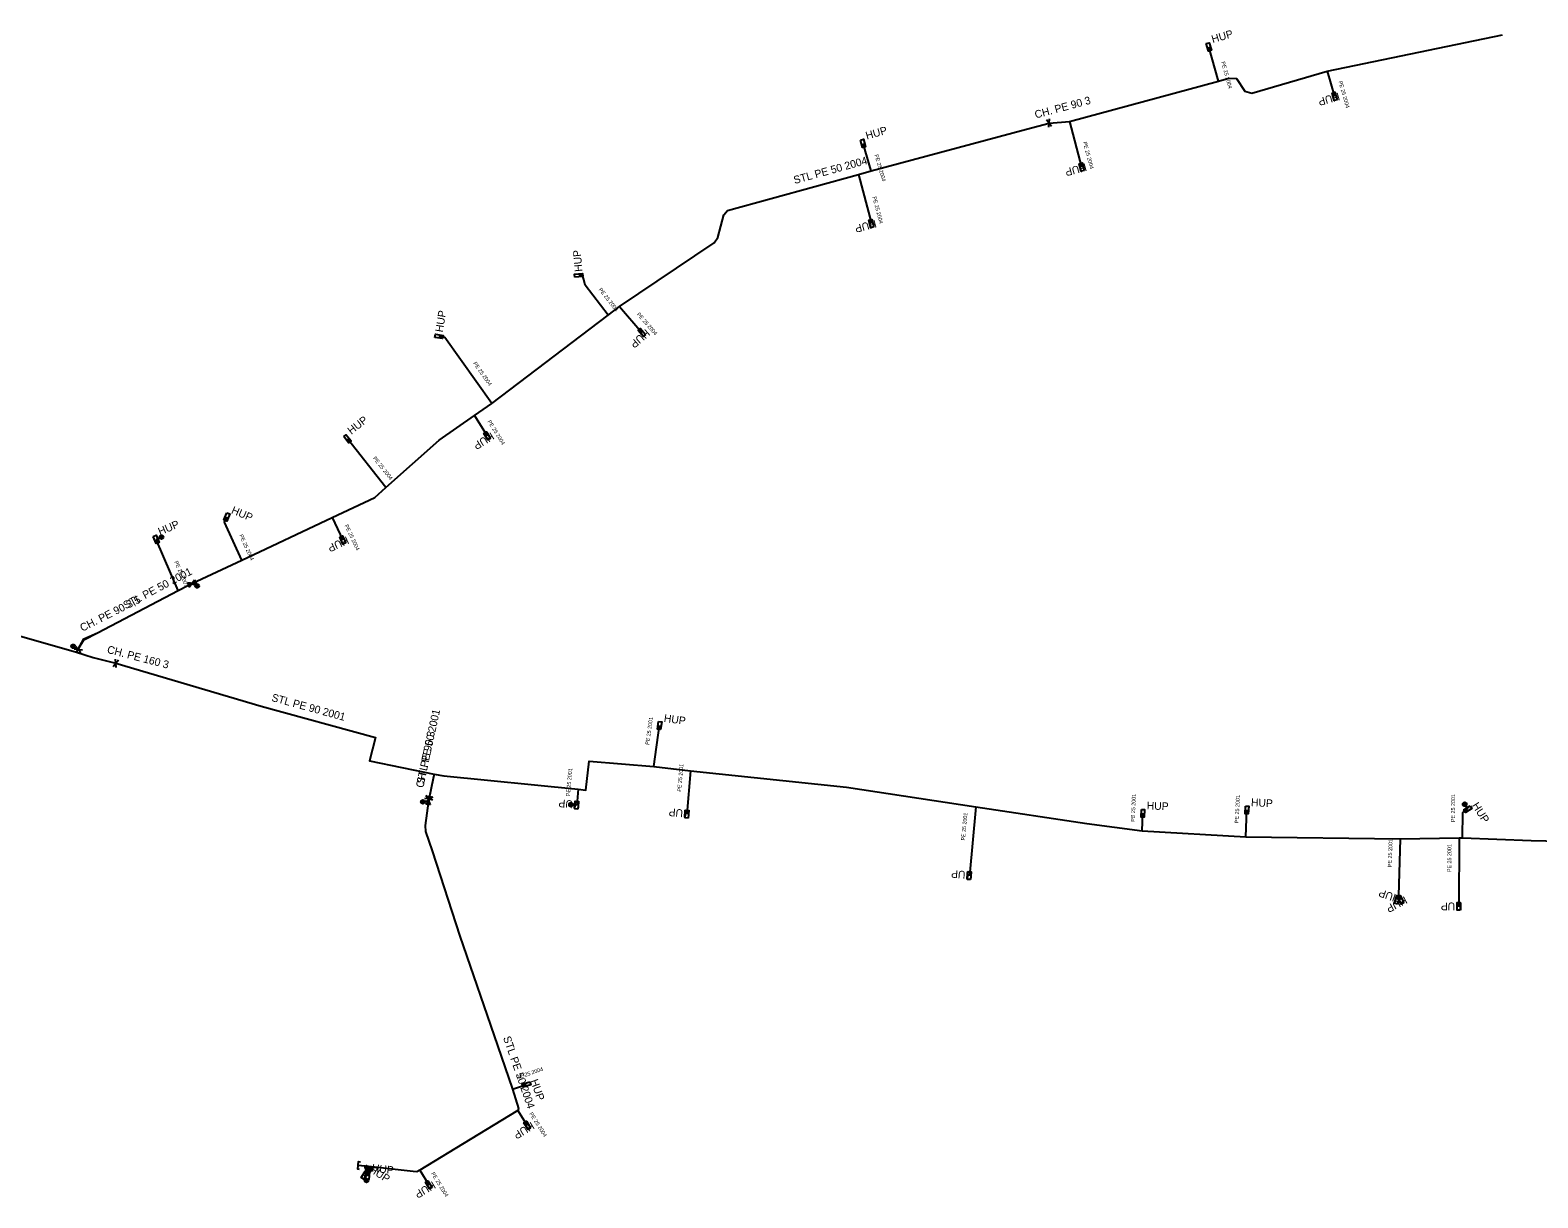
# Model space of a CAD drawing. Extents: x -724831 to -724223, y -1048957 to -1048806.
# Drawn here: x -724613.1 to -724418.3, y -1048956.6 to -1048805.7 of the extents above; entities that cross this region are included whole.
import ezdxf

# ---------------------------------------------------------------- set-up
doc = ezdxf.new("R2010")
doc.units = 0
for name, color, linetype in [('ST OP Chráni_ka - provoz', 7, 'Continuous'), ('ST Úsek p_ípojky - provoz', 7, 'Continuous'), ('ST Úsek plynovodu - provoz', 7, 'Continuous'), ('ST_HUP_22_23_popis', 7, 'Continuous'), ('Vrstva 1', 7, 'Continuous')]:
    doc.layers.add(name, color=color, linetype=linetype)

msp = doc.modelspace()

# ---------------------------------------------------------------- linework, layer by layer
at = {"layer": 'ST OP Chráni_ka - provoz'}
for points in [[(-724484.31, -1048818.51), (-724481.41, -1048817.73)], [(-724606.84, -1048885.7), (-724606.12, -1048884.49)], [(-724606.12, -1048884.49), (-724604.36, -1048883.6)], [(-724604.91, -1048886.77), (-724601.99, -1048887.53)], [(-724560.98, -1048902.42), (-724561.59, -1048905.36)]]:
    msp.add_lwpolyline(points, dxfattribs=at)
at = {"layer": 'ST Úsek p_ípojky - provoz'}
for points in [[(-724459.52, -1048812.33), (-724460.76, -1048807.9)], [(-724445.46, -1048811.01), (-724444.52, -1048814.28)], [(-724478.78, -1048817.53), (-724477.21, -1048823.42)], [(-724504.41, -1048823.92), (-724505.45, -1048820.37)], [(-724506.05, -1048824.38), (-724504.37, -1048830.72)], [(-724538.36, -1048842.55), (-724541.37, -1048838.66), (-724541.53, -1048837.96), (-724541.72, -1048837.36), (-724542.19, -1048837.4)], [(-724536.91, -1048841.45), (-724534.02, -1048844.79)], [(-724553.42, -1048853.95), (-724559.47, -1048845.43), (-724560.24, -1048845.31)], [(-724555.66, -1048855.51), (-724554.02, -1048858.15)], [(-724567.1, -1048864.83), (-724572.07, -1048858.52)], [(-724585.7, -1048874.22), (-724587.94, -1048869.29), (-724587.66, -1048868.62)], [(-724574.04, -1048868.71), (-724572.68, -1048871.61)], [(-724593.95, -1048878.12), (-724596.78, -1048871.53)], [(-724532.47, -1048900.89), (-724531.73, -1048895.59)], [(-724527.72, -1048901.44), (-724528.2, -1048907.02)], [(-724542.25, -1048903.78), (-724542.44, -1048905.86)], [(-724490.88, -1048906.1), (-724491.71, -1048914.98)], [(-724456, -1048909.98), (-724455.84, -1048906.49)], [(-724427.98, -1048910.08), (-724427.96, -1048906.8), (-724427.3, -1048906.39)], [(-724469.39, -1048909.2), (-724469.3, -1048906.92)], [(-724436.03, -1048910.2), (-724436.25, -1048917.59)], [(-724428.43, -1048910.09), (-724428.47, -1048918.95)], [(-724436.25, -1048917.59), (-724436.43, -1048918.1)], [(-724436.25, -1048917.59), (-724435.98, -1048918.1)], [(-724550.73, -1048942.58), (-724548.93, -1048941.97)], [(-724550.05, -1048945.3), (-724548.83, -1048947.24)], [(-724569.49, -1048953.1), (-724569.85, -1048953.65)], [(-724569.39, -1048953.11), (-724569.49, -1048953.1)], [(-724569.4, -1048953.21), (-724569.46, -1048953.71)], [(-724569.33, -1048952.57), (-724569.39, -1048953.11), (-724569.4, -1048953.21)], [(-724562.71, -1048953.04), (-724561.57, -1048954.92)]]:
    msp.add_lwpolyline(points, dxfattribs=at)
at = {"layer": 'ST Úsek plynovodu - provoz'}
for points in [[(-724592.17, -1048877.22), (-724585.7, -1048874.22), (-724574.04, -1048868.71), (-724568.53, -1048866.11), (-724567.1, -1048864.83), (-724560.21, -1048858.69), (-724555.66, -1048855.51), (-724553.42, -1048853.95), (-724538.36, -1048842.55), (-724536.91, -1048841.45), (-724524.69, -1048833.2), (-724524.22, -1048832.5), (-724523.43, -1048829.58), (-724522.95, -1048829.04), (-724506.05, -1048824.38), (-724504.41, -1048823.92), (-724484.31, -1048818.51), (-724481.41, -1048817.73), (-724478.78, -1048817.53), (-724459.52, -1048812.33), (-724458.17, -1048811.95), (-724457.19, -1048811.98), (-724456.11, -1048813.59), (-724455.2, -1048813.85), (-724445.46, -1048811.01), (-724422.83, -1048806.33)], [(-724755.26, -1048907.64), (-724751.23, -1048905.91), (-724751.02, -1048905.85), (-724751.07, -1048905.68), (-724752.41, -1048900.83), (-724752.44, -1048900.67), (-724733.73, -1048896.27), (-724719.78, -1048892.98), (-724717.34, -1048892.45), (-724709.54, -1048890.62), (-724698.43, -1048887.4), (-724693.82, -1048886.04), (-724681.03, -1048882.26), (-724668.37, -1048878.78), (-724657.94, -1048876.45), (-724653.02, -1048875.9), (-724646.98, -1048876.12), (-724638.5, -1048877.54), (-724622.14, -1048881.8), (-724607.06, -1048886.1)], [(-724607.06, -1048886.1), (-724606.84, -1048885.7), (-724606.12, -1048884.36), (-724604.36, -1048883.6), (-724593.95, -1048878.12), (-724592.71, -1048877.47)], [(-724592.71, -1048877.47), (-724592.17, -1048877.22)], [(-724607.06, -1048886.1), (-724604.91, -1048886.77), (-724601.99, -1048887.53), (-724583.23, -1048893.08), (-724568.46, -1048897.13), (-724569.2, -1048900.16), (-724560.87, -1048901.88)], [(-724560.87, -1048901.88), (-724559.61, -1048902.09), (-724542.25, -1048903.78), (-724541.28, -1048903.95), (-724540.82, -1048900.17), (-724532.47, -1048900.89), (-724527.72, -1048901.44), (-724507.58, -1048903.55), (-724490.88, -1048906.1), (-724476.53, -1048908.25), (-724469.39, -1048909.2), (-724456, -1048909.98), (-724436.03, -1048910.2), (-724428.43, -1048910.09), (-724427.98, -1048910.08), (-724419.12, -1048910.44), (-724405.91, -1048910.73)], [(-724560.87, -1048901.88), (-724560.98, -1048902.42), (-724561.52, -1048904.9)], [(-724561.52, -1048904.9), (-724561.58, -1048905.29)], [(-724561.58, -1048905.29), (-724562.02, -1048908.5), (-724561.96, -1048909.27), (-724561.13, -1048911.75), (-724557.56, -1048922.78), (-724552.68, -1048936.91), (-724550.73, -1048942.58), (-724549.96, -1048945.05), (-724550.05, -1048945.3), (-724556.2, -1048949.05), (-724562.71, -1048953.04), (-724563.11, -1048953.23), (-724563.59, -1048953.2), (-724569.33, -1048952.57), (-724570.69, -1048952.42)]]:
    msp.add_lwpolyline(points, dxfattribs=at)
at = {"layer": 'Vrstva 1'}
for p, q in [((-724481.46, -1048818.27), (-724481.36, -1048817.19)), ((-724481.08, -1048818.16), (-724481.74, -1048817.3)), ((-724596.78, -1048871.53), (-724596.32, -1048871.33)), ((-724591.59, -1048877.28), (-724592.75, -1048877.16)), ((-724592.75, -1048877.16), (-724592.5, -1048877.7)), ((-724592.5, -1048877.7), (-724591.84, -1048876.74)), ((-724592.17, -1048877.22), (-724591.71, -1048877.43)), ((-724591.84, -1048876.74), (-724591.59, -1048877.28)), ((-724606.84, -1048885.7), (-724607.28, -1048885.46)), ((-724607.19, -1048885.31), (-724606.51, -1048886.14)), ((-724607.39, -1048885.66), (-724606.32, -1048885.79)), ((-724602.33, -1048887.95), (-724601.65, -1048887.11)), ((-724601.94, -1048888.07), (-724602.04, -1048886.99)), ((-724562.05, -1048904.99), (-724560.99, -1048904.81)), ((-724561.97, -1048904.6), (-724561.07, -1048905.2)), ((-724561.95, -1048905.74), (-724561.21, -1048904.84)), ((-724561.21, -1048904.84), (-724561.8, -1048904.75)), ((-724561.8, -1048904.75), (-724561.36, -1048905.83)), ((-724561.58, -1048905.29), (-724562.07, -1048905.39)), ((-724561.36, -1048905.83), (-724561.95, -1048905.74)), ((-724542.44, -1048905.86), (-724542.94, -1048905.82)), ((-724427.3, -1048906.39), (-724427.57, -1048905.96)), ((-724569.85, -1048953.65), (-724569.69, -1048954.13))]:
    msp.add_line(p, q, dxfattribs=at)
for points in [[(-724461.09, -1048807.47), (-724460.71, -1048807.36), (-724460.43, -1048808.33), (-724460.81, -1048808.44)], [(-724444.19, -1048814.71), (-724444.57, -1048814.82), (-724444.85, -1048813.85), (-724444.47, -1048813.74)], [(-724505.78, -1048819.94), (-724505.4, -1048819.83), (-724505.12, -1048820.8), (-724505.5, -1048820.91)], [(-724476.89, -1048823.85), (-724477.27, -1048823.95), (-724477.53, -1048822.99), (-724477.15, -1048822.89)], [(-724504.05, -1048831.15), (-724504.43, -1048831.25), (-724504.69, -1048830.29), (-724504.31, -1048830.19)], [(-724542.67, -1048837.64), (-724542.71, -1048837.24), (-724541.71, -1048837.16), (-724541.67, -1048837.56)], [(-724533.54, -1048845.04), (-724533.84, -1048845.3), (-724534.5, -1048844.54), (-724534.2, -1048844.28)], [(-724560.77, -1048845.43), (-724560.7, -1048845.03), (-724559.71, -1048845.19), (-724559.78, -1048845.59)], [(-724572.54, -1048858.25), (-724572.22, -1048858), (-724571.6, -1048858.79), (-724571.92, -1048859.04)], [(-724553.59, -1048858.47), (-724553.92, -1048858.68), (-724554.45, -1048857.83), (-724554.12, -1048857.62)], [(-724587.65, -1048868.08), (-724587.28, -1048868.24), (-724587.67, -1048869.16), (-724588.04, -1048869)], [(-724597.16, -1048871.15), (-724596.79, -1048870.99), (-724596.4, -1048871.91), (-724596.77, -1048872.07)], [(-724572.29, -1048871.98), (-724572.65, -1048872.15), (-724573.07, -1048871.24), (-724572.71, -1048871.07)], [(-724531.86, -1048895.07), (-724531.46, -1048895.12), (-724531.6, -1048896.11), (-724532, -1048896.06)], [(-724542.28, -1048906.37), (-724542.68, -1048906.34), (-724542.6, -1048905.34), (-724542.2, -1048905.38)], [(-724528.04, -1048907.53), (-724528.44, -1048907.5), (-724528.36, -1048906.5), (-724527.96, -1048906.54)], [(-724469.48, -1048906.41), (-724469.08, -1048906.43), (-724469.12, -1048907.43), (-724469.52, -1048907.41)], [(-724456.01, -1048905.98), (-724455.61, -1048906), (-724455.67, -1048907), (-724456.06, -1048906.98)], [(-724426.98, -1048905.95), (-724426.77, -1048906.29), (-724427.62, -1048906.82), (-724427.83, -1048906.48)], [(-724491.55, -1048915.49), (-724491.95, -1048915.46), (-724491.87, -1048914.46), (-724491.47, -1048914.5)], [(-724436.4, -1048918.64), (-724436.78, -1048918.51), (-724436.46, -1048917.56), (-724436.08, -1048917.69)], [(-724435.57, -1048918.45), (-724435.92, -1048918.64), (-724436.39, -1048917.75), (-724436.04, -1048917.56)], [(-724428.27, -1048919.45), (-724428.67, -1048919.45), (-724428.67, -1048918.45), (-724428.27, -1048918.45)], [(-724548.52, -1048941.62), (-724548.39, -1048942), (-724549.34, -1048942.32), (-724549.47, -1048941.94)], [(-724548.4, -1048947.56), (-724548.73, -1048947.77), (-724549.26, -1048946.92), (-724548.93, -1048946.71)], [(-724569.74, -1048953.12), (-724569.41, -1048953.34), (-724569.96, -1048954.18), (-724570.29, -1048953.96)], [(-724568.85, -1048952.77), (-724569.84, -1048952.66), (-724569.45, -1048953.71)], [(-724568.8, -1048952.97), (-724569.62, -1048952.41), (-724569.77, -1048953.51)], [(-724569.6, -1048953.19), (-724569.2, -1048953.24), (-724569.32, -1048954.23), (-724569.72, -1048954.18)], [(-724569.69, -1048952.78), (-724569.43, -1048953.48), (-724569.02, -1048952.85)], [(-724569.55, -1048952.58), (-724569.64, -1048953.33), (-724568.99, -1048952.96)], [(-724569.41, -1048953.26), (-724569.19, -1048952.93), (-724569.54, -1048952.89)], [(-724569.52, -1048953.14), (-724569.18, -1048952.95), (-724569.47, -1048952.75)], [(-724561.14, -1048955.25), (-724561.48, -1048955.45), (-724562, -1048954.59), (-724561.66, -1048954.39)]]:
    msp.add_lwpolyline(points, close=True, dxfattribs=at)
msp.add_lwpolyline([(-724570.49, -1048952.94), (-724570.74, -1048952.92), (-724570.64, -1048951.92), (-724570.39, -1048951.95)], dxfattribs=at)
for centre, radius in [((-724596.09, -1048871.23), 0.249), ((-724596.14, -1048871.14), 0.0614), ((-724596.06, -1048871.33), 0.0614), ((-724591.49, -1048877.54), 0.249), ((-724591.54, -1048877.62), 0.0614), ((-724591.45, -1048877.44), 0.0614), ((-724607.5, -1048885.34), 0.249), ((-724607.54, -1048885.44), 0.0614), ((-724607.44, -1048885.25), 0.0614), ((-724562.32, -1048905.44), 0.249), ((-724562.33, -1048905.33), 0.0614), ((-724562.29, -1048905.54), 0.0614), ((-724543.19, -1048905.8), 0.249), ((-724543.19, -1048905.9), 0.0614), ((-724543.17, -1048905.7), 0.0614), ((-724427.7, -1048905.75), 0.249), ((-724427.78, -1048905.82), 0.0614), ((-724427.61, -1048905.71), 0.0614), ((-724569.6, -1048954.36), 0.249), ((-724569.7, -1048954.38), 0.0614), ((-724569.51, -1048954.31), 0.0614)]:
    msp.add_circle(centre, radius, dxfattribs=at)

# ---------------------------------------------------------------- texts
at = {"layer": 'ST OP Chráni_ka - provoz'}
for s, rotation, p in [('CH. PE 90 3', 15.0727, (-724483.12, -1048817.15)), ('CH. PE 90 3,5', 26.7207, (-724606.32, -1048883.47)), ('CH. PE 160 3', 345.3927, (-724603.2, -1048886.18)), ('CH. PE 90 3', 78.2784, (-724562.26, -1048903.69))]:
    msp.add_text(s, height=1, rotation=rotation, dxfattribs=at).set_placement(p)
at = {"layer": 'ST Úsek p_ípojky - provoz'}
for s, rotation, p in [('PE 25 2004', 285.6374, (-724459.18, -1048809.85)), ('PE 25 2004', 286.0379, (-724444.03, -1048812.37)), ('PE 25 2004', 284.9254, (-724477.03, -1048820.22)), ('PE 25 2004', 286.3284, (-724503.97, -1048821.86)), ('PE 25 2004', 284.8414, (-724504.24, -1048827.29)), ('PE 25 2004', 307.7319, (-724539.63, -1048839.27)), ('PE 25 2004', 310.8686, (-724534.71, -1048842.47)), ('PE 25 2004', 305.3783, (-724555.86, -1048848.79)), ('PE 25 2004', 301.8491, (-724553.99, -1048856.3)), ('PE 25 2004', 308.2253, (-724568.8, -1048861.06)), ('PE 25 2004', 295.125, (-724572.45, -1048869.74)), ('PE 25 2004', 294.4352, (-724586.06, -1048871.01)), ('PE 25 2001', 293.2332, (-724594.45, -1048874.43)), ('PE 25 2001', 82.0516, (-724533.09, -1048898.1)), ('PE 25 2001', 85.0826, (-724528.96, -1048904.14)), ('PE 25 2001', 84.7782, (-724543.34, -1048904.73)), ('PE 25 2001', 87.7395, (-724470.34, -1048908.02)), ('PE 25 2001', 87.3587, (-724456.92, -1048908.19)), ('PE 25 2001', 89.6506, (-724428.97, -1048908.05)), ('PE 25 2001', 84.6596, (-724492.29, -1048910.45)), ('PE 25 2001', 88.2948, (-724437.14, -1048913.87)), ('PE 25 2001', 89.7478, (-724429.45, -1048914.52)), ('PE 25 2004', 18.7209, (-724550.15, -1048941.33)), ('PE 25 2004', 302.1644, (-724548.59, -1048945.74)), ('PE 25 2004', 301.2319, (-724561.28, -1048953.46))]:
    msp.add_text(s, height=0.5, rotation=rotation, dxfattribs=at).set_placement(p)
at = {"layer": 'ST Úsek plynovodu - provoz'}
for s, rotation, p in [('STL PE 50 2004', 15.4156, (-724514.27, -1048825.61)), ('STL PE 50 2001', 27.7631, (-724600.72, -1048880.56)), ('STL PE 90 2001', 344.6661, (-724581.95, -1048892.39)), ('STL PE 50 2001', 77.716, (-724562.17, -1048903.18)), ('STL PE 50 2004', 289.0531, (-724551.97, -1048935.91))]:
    msp.add_text(s, height=1, rotation=rotation, dxfattribs=at).set_placement(p)
at = {"layer": 'ST_HUP_22_23_popis'}
for rotation, p in [(16, (-724460.26, -1048807.4)), (196, (-724444.02, -1048813.78)), (16, (-724504.95, -1048819.87)), (195, (-724476.71, -1048822.92)), (195, (-724503.87, -1048830.22)), (95, (-724541.69, -1048836.9)), (81, (-724559.74, -1048844.81)), (221, (-724533.52, -1048844.29)), (38, (-724571.57, -1048858.02)), (212, (-724553.52, -1048857.65)), (337, (-724587.16, -1048868.12)), (23, (-724596.28, -1048871.03)), (205, (-724572.18, -1048871.11)), (352, (-724531.23, -1048895.09)), (175, (-724541.94, -1048905.36)), (175, (-724527.7, -1048906.52)), (358, (-724468.8, -1048906.42)), (357, (-724455.34, -1048905.99)), (302, (-724426.8, -1048905.89)), (175, (-724491.21, -1048914.48)), (161, (-724435.93, -1048917.6)), (208, (-724435.48, -1048917.6)), (180, (-724427.97, -1048918.45)), (289, (-724548.43, -1048941.47)), (212, (-724548.33, -1048946.74)), (326.79, (-724569.35, -1048953.15)), (353.16, (-724568.96, -1048953.21)), (211, (-724561.07, -1048954.42))]:
    msp.add_text('HUP', height=1, rotation=rotation, dxfattribs=at).set_placement(p)

doc.saveas('drawing.dxf')
